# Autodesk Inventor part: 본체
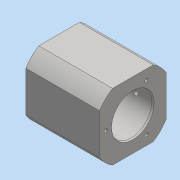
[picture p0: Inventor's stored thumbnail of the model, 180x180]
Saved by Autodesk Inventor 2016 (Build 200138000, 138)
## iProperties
Created: 2020-02
Part Number: 본체
Material: 일반
Document SubType Name: Modeling
Designer: Administrator
Density: 1 g/cm^3
Appearance: 기본값
Mass: 199.224 g
Surface Area: 342.681 cm^2
Volume: 199.224 cm^3
Author: Administrator
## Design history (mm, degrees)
sketch "스케치1"
  geometry: L1 (-19.551, 32)-(19.551, 32); L2 (32, 19.551)-(32, -19.551); L3 (19.551, -32)-(-19.551, -32); L4 (-32, -19.551)-(-32, 19.551); L5 (-32, 32)-(32, -32); L6 (32, 32)-(-32, -32); A1 r 37.5 centre (0, 0) between (19.551, -32) and (32, -19.551); A2 r 37.5 centre (0, 0) between (-32, -19.551) and (-19.551, -32); A3 r 37.5 centre (0, 0) between (32, 19.551) and (19.551, 32); A4 r 37.5 centre (0, 0) between (-19.551, 32) and (-32, 19.551); 1 further point
  constraints: 12 end point, 8 point on circle, 4 centre point, 2 midpoint, 2 parallel, 1 coincident, 1 horizontal, 1 perpendicular
  dimensions: "d0" = 64 distance of L6.start L5.end
extrude "돌출1" new body sketch "스케치1" distance "d2" = 71; taper "d3" = 0 deg
sketch "스케치2"
  geometry: C1 r 14 at (0, 0); 1 further point
  constraints: 1 centre point, 1 coincident
  dimensions: "d4" = 28 diameter of C1
extrude "돌출2" join sketch "스케치2" distance "d5" = 12; taper "d6" = 0 deg
hole "구멍1" diameter "d9" = 8.917; stored, may be unused: countersink angle "d13" = 90 deg, drill point angle "d15" = 118 deg; dims "d7" = 10, "d8" = 10, "d10" = 14, "d11" = 4, "d12" = 2, "d14" = 17
sketch "스케치3"
  geometry: C1 r 4.458 at (0, 0) reference; C2 r 20 at (0, 0); 1 further point
  constraints: 1 centre point, 1 coincident
  dimensions: "d16" = 40 diameter of C2
extrude "돌출3" cut sketch "스케치3" distance "d17" = 62; taper "d18" = 0 deg
sketch "스케치4"
  geometry: L1 (-37.283, 0)-(46.134, 0); L2 (0, 0)-(46.451, 26.819); L3 (0, 0)-(-47.571, 27.465); L4 (0, 0)-(0, 48.754); C1 r 4.458 at (0, 0) reference; A1 r 26 centre (0, 0) between (-22.517, 13) and (0, -26); 2 further points
  constraints: 8 end point, 2 point on circle, 1 centre point, 1 coincident, 1 horizontal, 1 midpoint, 1 point on line, 1 vertical
  dimensions: "d19" = 52 diameter of A1; "d20" = 60 deg angle of L4 L2; "d21" = 60 deg angle of L4 L3
hole "구멍2" sketch "스케치4" at (-22.517, 13), (23.226, 13.409), (0, -26) diameter "d22" = 3.242; stored, may be unused: countersink angle "d26" = 90 deg, drill point angle "d28" = 118 deg; dims "d23" = 8, "d24" = 4, "d25" = 2, "d27" = 11.8
chamfer "모따기1" distance "d36" = 1.8; stored, may be unused: second distance "d37" = 2, angle "d38" = 15 deg
chamfer "모따기2" distance "d39" = 1; stored, may be unused: second distance "d40" = 2, angle "d41" = 15 deg
sketch "스케치6"
  geometry: L1 (71, 39.102)-(71, 0) reference; L2 (0, 0)-(0, 39.102) reference; 3 further points
  constraints: 1 horizontal alignment, 1 midpoint
  dimensions: "d42" = 17 distance from line of L1 point (54, 19.551)
hole "구멍4" sketch "스케치6" at (54, 19.551) diameter "d43" = 8.917; stored, may be unused: countersink angle "d47" = 90 deg, drill point angle "d49" = 118 deg; dims "d44" = 6, "d45" = 4, "d46" = 2, "d48" = 9
sketch "스케치7"
  geometry: C1 r 4.458 at (54, 19.551) reference; C2 r 2 at (54, 19.551); 1 further point
  constraints: 1 centre point, 1 coincident
  dimensions: "d50" = 4 diameter of C2
extrude "돌출4" cut sketch "스케치7" distance "d51" = 20; taper "d52" = 0 deg
sketch "스케치8"
  geometry: C1 r 4.458 at (0, 0) reference; C2 r 2 at (0, 0); 1 further point
  constraints: 1 centre point, 1 coincident
  dimensions: "d53" = 4 diameter of C2
extrude "돌출5" cut sketch "스케치8" distance "d54" = 40; taper "d55" = 0 deg
sketch "스케치9"
  geometry: L1 (0, 0)-(0, 39.102) reference; 3 further points
  constraints: 1 horizontal alignment, 1 midpoint, 1 other
  dimensions: "d56" = 20 distance from line of L1 point (20, 19.551)
feature "엠보싱1" sketch "스케치9" dims "d57" = 0.5, "d58" = 0
sketch "스케치10"
  geometry: C1 r 14 at (0, 0) reference; C2 r 2 at (0, 0) reference; C3 r 1.621 at (0, -26) reference; A1 r 26 centre (0, 0) between (-26, 0) and (0, 26); 3 further points
  constraints: 3 point on circle, 2 coincident, 1 centre point
  dimensions: "d59" = 52 diameter of A1
hole "구멍5" sketch "스케치10" at (-26, 0), (0, 26), (26, 0), (0, -26) diameter "d60" = 3.242; stored, may be unused: countersink angle "d64" = 90 deg, drill point angle "d66" = 118 deg; dims "d61" = 10, "d62" = 4, "d63" = 2, "d65" = 12
node "솔리드1"
other parameters: "d1" = 75
